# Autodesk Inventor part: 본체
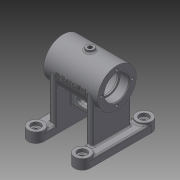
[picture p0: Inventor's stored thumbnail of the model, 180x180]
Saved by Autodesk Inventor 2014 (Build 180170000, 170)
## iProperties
Created: 2015-11
Part Number: 본체
Material: 일반
Document SubType Name: Modeling
Designer: USER
Density: 1 g/cm^3
Appearance: 기본값
Author: USER
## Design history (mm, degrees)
sketch "스케치2"
  geometry: L1 (0, 0)-(99.691, 0); L2 (0, 0)-(0, 25); L3 (0, 25)-(70, 25); L4 (70, 25)-(70, 0); L5 (0, 16)-(12, 16); L6 (12, 16)-(12, 14); L7 (12, 14)-(14, 14); L8 (14, 14)-(14, 21); L9 (14, 21)-(56, 21); L10 (56, 21)-(56, 14); L11 (56, 14)-(58, 14); L12 (58, 14)-(58, 16); L13 (58, 16)-(70, 16)
  constraints: 26 end point, 8 perpendicular, 4 parallel, 3 point on line, 1 horizontal
  dimensions: "d0" = 50 diameter of L3 L1; "d1" = 70 distance of L3.end L2.end; "d2" = 32 diameter of L5 L1; "d3" = 12 distance of L5.start L5.end; "d4" = 2 distance of L6.end L7.end; "d5" = 28 diameter of L7 L1; "d6" = 42 diameter of L9 L1; "d7" = 42 distance of L8.end L9.end; "d8" = 2 distance of L10.end L11.end; "d9" = 28 diameter of L11 L1; "d10" = 32 diameter of L13 L1
revolve "회전1" sketch "스케치2" stored, may be unused: angle "d11" = 90 deg
node "작업 평면1"
sketch "스케치3"
  geometry: L1 (5, -40)-(-15, -40); L2 (-15, -40)-(-15, 40); L3 (-15, 40)-(5, 40); L4 (5, 40)-(5, -40); L5 (-55, -40)-(-75, -40); L6 (-75, -40)-(-75, 40); L7 (-75, 40)-(-55, 40); L8 (-55, 40)-(-55, -40); L9 (0, 25)-(-70, 25) reference; L10 (-35, 25)-(-35, -27.416); 3 further points
  constraints: 18 end point, 4 parallel, 3 midpoint, 3 perpendicular, 2 horizontal, 2 horizontal alignment
  dimensions: "d19" = 20 distance of L2.end L3.end; "d20" = 80 distance of L1.end L2.end; "d21" = 20 distance of L6.end L7.end; "d22" = 80 distance of L5.end L6.end; "d24" = 80 distance between parallel lines of L6 L4; "d27" = 40 distance between parallel lines of L4 L10
extrude "돌출1" join sketch "스케치3" distance "d28" = 10; taper "d29" = 0 deg
sketch "스케치4"
  geometry: L1 (-5, -40)-(15, -40) reference; L2 (15, 40)-(-5, 40) reference; L3 (55, -40)-(75, -40) reference; L4 (75, -40)-(75, 40) reference; L5 (75, 40)-(55, 40) reference; L6 (55, 40)-(55, -40) reference; C1 r 10 at (5, 40); C2 r 10 at (65, 40); C3 r 10 at (5, -40); C4 r 10 at (65, -40); 1 further point
  constraints: 4 centre point, 4 midpoint
  dimensions: "d30" = 20 diameter of C1; "d31" = 20 diameter of C2; "d32" = 20 diameter of C3; "d33" = 20 diameter of C4
extrude "돌출2" join sketch "스케치4" distance "d34" = 13; taper "d35" = 0 deg
sketch "스케치6"
  geometry: L1 (10, 80)-(10, 0) reference; L2 (68, 65)-(10, 65); L3 (68, 15)-(10, 15); A1 r 25 centre (68, 40) between (68, 65) and (68, 15) reference; 1 further point
  constraints: 4 end point, 2 perpendicular, 2 point on circle, 2 point on line, 2 tangent
extrude "돌출3" join sketch "스케치6" distance "d36" = 8; taper "d37" = 0 deg
node "작업 평면2"
sketch "스케치7"
  geometry: L1 (75, -68)-(55, -68) reference; L2 (0, -25)-(70, -25) reference; L3 (55, 0)-(55, -58) reference; L4 (15, 0)-(15, -58) reference; L5 (55, -45)-(15, -45); 1 further point
  constraints: 2 end point, 2 point on line, 1 perpendicular
  dimensions: "d38" = 20 distance between parallel lines of L5 L2
feature "리브1" sketch "스케치7" dims "d39" = 1, "d40" = 8, "d41" = 0, "d42" = 0, "d43" = 1, "d44" = 1
node "작업 평면4"
sketch "스케치9"
  geometry: L1 (-70, 25)-(-70, -25) reference; C1 r 5 at (-35, 0); 2 further points
  constraints: 1 centre point, 1 horizontal alignment, 1 midpoint
  dimensions: "d47" = 10 diameter of C1; "d48" = 35 distance from line of C1.centre L1
extrude "돌출4" join sketch "스케치9" stored distance "d49" = 8; taper "d50" = 0 deg
node "작업 평면5"
sketch "스케치11"
  geometry: L1 (0, 0)-(40, 0) reference; L2 (60, -43.322)-(40, -43.322) reference; L3 (-15, 49.678)-(-15, -0.322) reference; L4 (12, -10.322)-(28, -10.322); L5 (12, -13.822)-(28, -13.822); L6 (28, -6.822)-(12, -6.822); A1 r 3.5 centre (12, -10.322) between (12, -6.822) and (12, -13.822); A2 r 3.5 centre (28, -10.322) between (28, -13.822) and (28, -6.822); 2 further points
  constraints: 8 end point, 4 point on circle, 4 tangent, 2 centre point, 2 parallel, 1 midpoint
  dimensions: "d55" = 7 distance of L5.end L6.start; "d56" = 23 dimension on A2 A1; "d57" = 33 distance from line of L2 point (20, -10.322); "d58" = 35 distance from line of point (20, -10.322) L3
extrude "돌출5" cut sketch "스케치11" distance "d59" = 8; taper "d60" = 0 deg
sketch "스케치13"
  geometry: C1 r 10 at (0, 0) reference; C2 r 10 at (0, 80) reference; C3 r 10 at (60, 80) reference; C4 r 10 at (60, 0) reference; 5 further points
  constraints: 4 coincident
hole "구멍1" sketch "스케치13" at (0, 80), (60, 80), (60, 0), (0, 0) diameter "d61" = 6; stored, may be unused: countersink angle "d65" = 90 deg, drill point angle "d67" = 0 deg; dims "d62" = 6, "d63" = 12, "d64" = 4, "d66" = 30
sketch "스케치14"
  geometry: C1 r 16 at (0, 0) reference; 1 further point
  constraints: 1 horizontal alignment
  dimensions: "d68" = 20 distance of C1.centre point (-20, 0)
hole "구멍2" sketch "스케치14" at (-20, 0) diameter "d69" = 3.459; stored, may be unused: countersink angle "d73" = 90 deg, drill point angle "d75" = 118 deg; dims "d70" = 8, "d71" = 12, "d72" = 4, "d74" = 10
node "작업 평면6"
node "작업 평면7"
sketch "스케치15"
  geometry: L1 (0, 0)-(24.249, 14); L2 (-54.163, 0)-(54.163, 0); L3 (24.249, 14)-(21.249, 19.196); L4 (21.249, 19.196)-(18.018, 17.331); A1 r 25 centre (0, 0) between (24.678, 4) and (0, 25) reference; A2 r 25 centre (0, 0) between (21.651, 12.5) and (18.018, 17.331); 2 further points
  constraints: 8 end point, 4 point on circle, 2 coincident, 2 perpendicular, 1 centre point, 1 concentric, 1 horizontal, 1 midpoint, 1 point on line
  dimensions: "d79" = 30 deg angle of L2 L1; "d84" = 6 distance of L1.end L3.end; "d86" = 28 distance from line of point (0, 0) L3
revolve "회전2" sketch "스케치15" stored, may be unused: angle "d87" = 90 deg
sketch "스케치16"
  geometry: C1 r 5 at (0, 0) reference; 2 further points
  constraints: 1 coincident
hole "구멍3" sketch "스케치16" at (0, 0) diameter "d88" = 5.188; stored, may be unused: countersink angle "d92" = 90 deg, drill point angle "d94" = 118 deg; dims "d89" = 15, "d90" = 12, "d91" = 4, "d93" = 15
sketch "스케치17"
  geometry: C1 r 6 at (0, 0) reference; 2 further points
  constraints: 1 coincident
hole "구멍4" sketch "스케치17" at (0, 0) diameter "d95" = 5.188; stored, may be unused: countersink angle "d99" = 90 deg, drill point angle "d101" = 118 deg; dims "d96" = 15, "d97" = 12, "d98" = 4, "d100" = 15
node "작업 평면8"
sketch "스케치18"
  geometry: L1 (35, 25)-(-35, 25) reference; L2 (-35, 25)-(-35, -25) reference; 2 further points
  constraints: 1 other
  dimensions: "d102" = 25 distance from line of L1 point (0, 0); "d103" = 35 distance from line of L2 point (0, 0)
feature "엠보싱1" sketch "스케치18" dims "d104" = 0.5, "d105" = 0
fillet "모깎기1" dims "d106" = 2
fillet "모깎기2" dims "d107" = 2
fillet "모깎기3" dims "d108" = 2
fillet "모깎기4" dims "d109" = 2
fillet "모깎기5" dims "d110" = 2
fillet "모깎기6" dims "d111" = 2
fillet "모깎기7" dims "d112" = 0.3
chamfer "모따기1" distance "d113" = 1; stored, may be unused: second distance "d114" = 2, angle "d115" = 45 deg
chamfer "모따기2" distance "d116" = 1; stored, may be unused: second distance "d117" = 2, angle "d118" = 45 deg
chamfer "모따기3" distance "d119" = 1; stored, may be unused: second distance "d120" = 2, angle "d121" = 45 deg
chamfer "모따기4" distance "d122" = 1; stored, may be unused: second distance "d123" = 2, angle "d124" = 45 deg
fillet "모깎기8" dims "d125" = 3
fillet "모깎기9" dims "d126" = 3
fillet "모깎기10" dims "d127" = 0.3
fillet "모깎기11" dims "d128" = 0.3
chamfer "모따기5" distance "d129" = 1; stored, may be unused: second distance "d130" = 2, angle "d131" = 45 deg
chamfer "모따기6" distance "d132" = 1; stored, may be unused: second distance "d133" = 2, angle "d134" = 45 deg
node "솔리드1"
mirror "대칭1"
pattern_circular "원형 패턴1" dims angle "d77" = 360 deg
mirror "대칭2"
node "투영된 루프1"
other parameters: "d12" = -68, "d46" = 28
